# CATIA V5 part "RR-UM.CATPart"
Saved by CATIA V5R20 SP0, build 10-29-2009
Part number: RR-UM
Revision: ANY
Definition: UNKNOWN
Nomenclature: RR-UM
Source: Unknown
Bounding box of the stored display mesh (mm): x -14.408 to 14.38, y 0 to 3, z -14.21 to 14.3
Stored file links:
  C:\Users\Utente\Desktop\IO LAVORO\3D X SITO CF\X SITO\3D files UM\UM043642 PRODUCT\RR-UM.CATPart
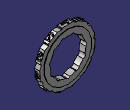
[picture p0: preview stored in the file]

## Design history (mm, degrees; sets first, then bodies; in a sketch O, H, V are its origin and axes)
Body1 "MatrizC2" (main body)
  Solid1: solid without history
